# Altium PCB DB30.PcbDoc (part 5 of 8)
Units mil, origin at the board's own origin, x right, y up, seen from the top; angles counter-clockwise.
Board outline 3236.22 x 4456.69 mil, 8 copper layers (Top Layer, MidLayer1, MidLayer2, GND-Layer5, MidLayer3, VCC, MidLayer4, Bottom Layer), stack 61.8 mil thick; 219 components, 472 nets, 1811 pads, 1561 vias.
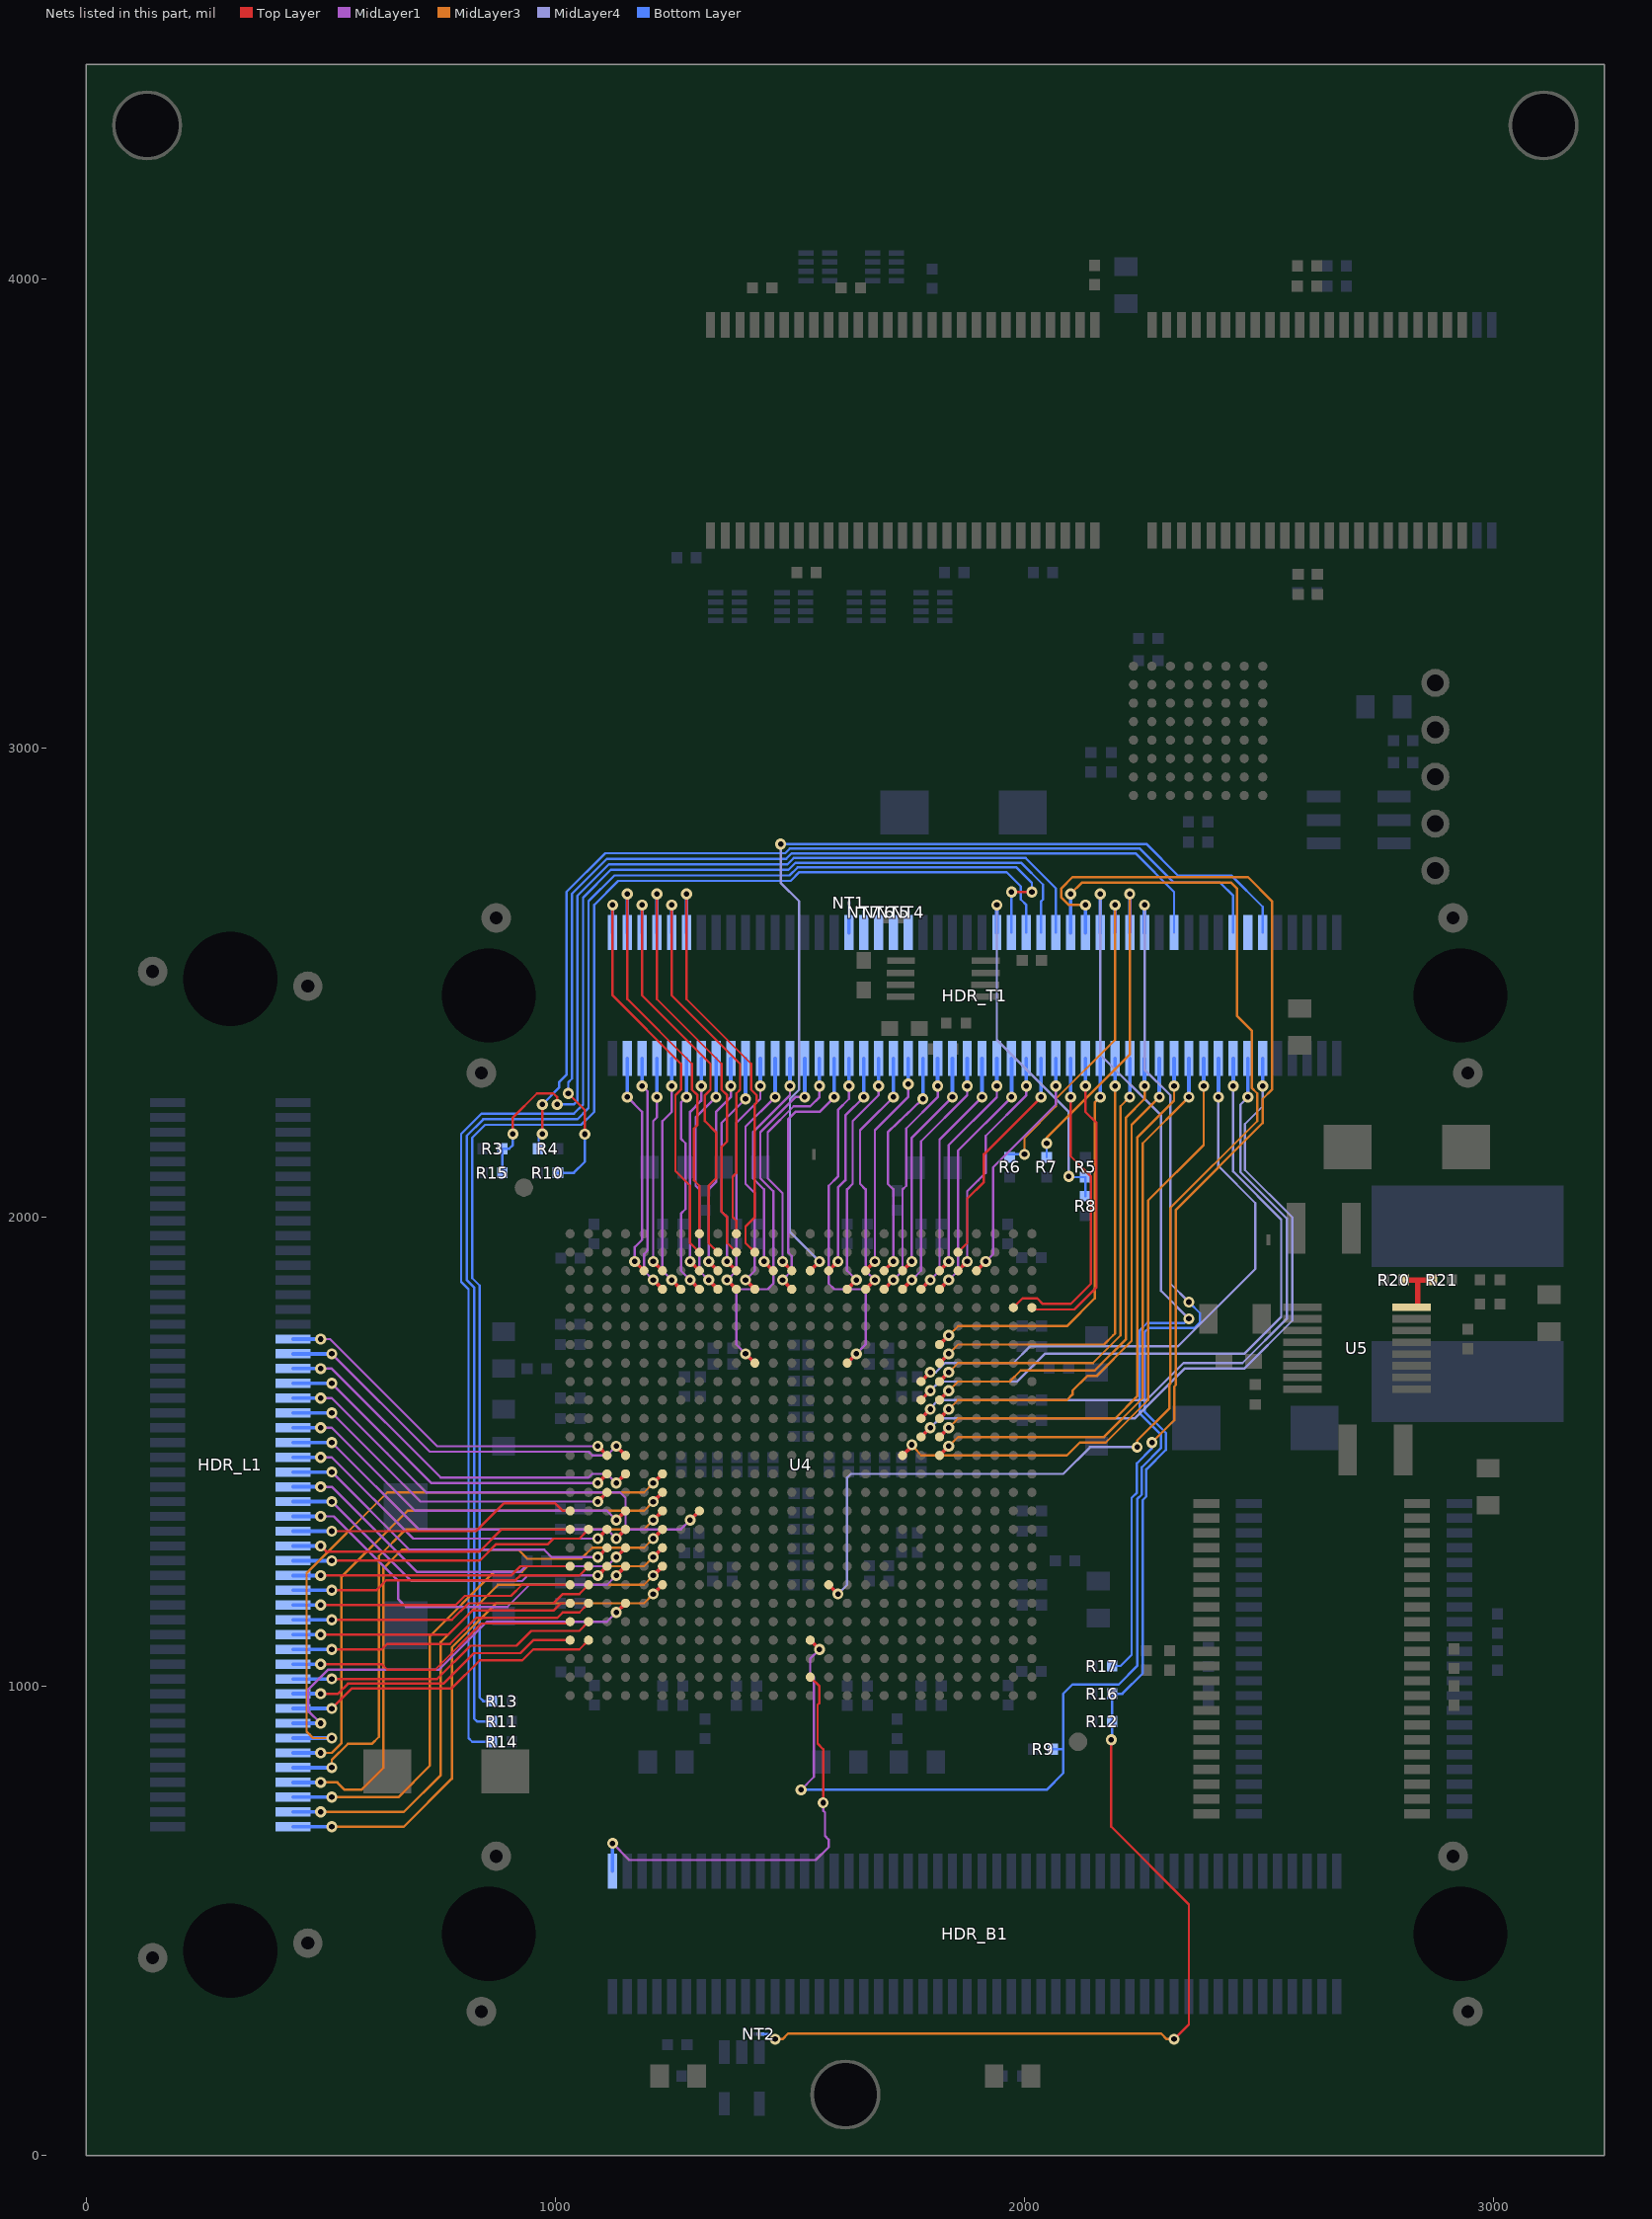
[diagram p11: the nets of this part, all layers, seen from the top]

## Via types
v1: diameter 23.62, hole 11.81, Top Layer to Bottom Layer, 944 vias
v2: diameter 23.62, hole 11.81, Top Layer to Bottom Layer, tented both sides, 477 vias
v3: diameter 27.56, hole 15.75, Top Layer to Bottom Layer, 139 vias
v4: diameter 23.62, hole 11.81, Top Layer to Bottom Layer, tented top, 1 vias

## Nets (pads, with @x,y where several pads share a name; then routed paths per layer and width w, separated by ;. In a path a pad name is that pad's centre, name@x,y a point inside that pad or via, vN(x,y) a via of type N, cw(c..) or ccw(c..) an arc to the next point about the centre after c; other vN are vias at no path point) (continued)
EXTEND_B16: HDR_L1.34 U4.N3 | length 772
  Top Layer w7.87: v1(1090.55,1511.81) U4.N3@1110.24,1492.13
  MidLayer1 w5: v2(500,1740.16) 519.68,1740.16 748.03,1511.81 956.69,1511.81 968.5,1511.81 v1(1090.55,1511.81)
  Bottom Layer w7.87: HDR_L1.34@440.94,1740.15 v2(500,1740.16)
EXTEND_B17: HDR_L1.36 U4.N4 | length 814.7
  Top Layer w7.87: v1(1129.92,1511.81) U4.N4@1149.61,1492.13
  MidLayer1 w5: v2(523.62,1708.66) 732.29,1500 956.69,1500 968.5,1500 1070.87,1500 1078.74,1492.13 1110.23,1492.13 v1(1129.92,1511.81)
  Bottom Layer w7.87: HDR_L1.36@440.94,1708.66 v2(523.62,1708.66)
EXTEND_B18: HDR_L1.38 U4.P4 | length 824.4
  Top Layer w7.87: v1(1129.92,1433.07) U4.P4@1149.61,1452.76
  MidLayer1 w5: v2(500,1677.17) 523.62,1677.17 755.91,1444.88 956.69,1444.88 968.5,1444.88 1070.87,1444.88 1078.74,1452.76 1110.23,1452.76 v1(1129.92,1433.07)
  Bottom Layer w7.87: HDR_L1.38@440.94,1677.16 v2(500,1677.17)
EXTEND_B19: HDR_L1.40 U4.P3 | length 765.5
  Top Layer w7.87: v1(1090.55,1433.07) U4.P3@1110.24,1452.76
  MidLayer1 w5: v2(523.62,1645.67) 736.22,1433.07 956.69,1433.07 968.5,1433.07 v1(1090.55,1433.07)
  Bottom Layer w7.87: HDR_L1.40@440.94,1645.67 v2(523.62,1645.67)
EXTEND_B20: HDR_L1.42 U4.T8 | length 1032.8
  Top Layer w7.87: v1(1287.4,1354.33) U4.T8@1307.09,1374.02
  MidLayer1 w5: v2(500,1614.17) 523.62,1614.17 641.73,1496.06 724.41,1413.39 956.69,1413.39 968.5,1413.39 1003.94,1413.39 1137.8,1413.39 1149.61,1401.57 1149.61,1342.52 1157.48,1334.65 1267.72,1334.65 v1(1287.4,1354.33)
  Bottom Layer w7.87: HDR_L1.42@440.94,1614.17 v2(500,1614.17)
EXTEND_B21: HDR_L1.44 U4.R3 | length 755.7
  Top Layer w7.87: v1(1090.55,1393.7) U4.R3@1110.24,1413.39
  MidLayer1 w5: v2(523.62,1582.68) 712.6,1393.7 956.69,1393.7 968.5,1393.7 v1(1090.55,1393.7)
  Bottom Layer w7.87: HDR_L1.44@440.94,1582.67 v2(523.62,1582.68)
EXTEND_B22: HDR_L1.46 U4.T4 | length 798.4
  Top Layer w7.87: v1(1129.92,1354.33) U4.T4@1149.61,1374.02
  MidLayer1 w5: v2(500,1551.18) 523.62,1551.18 700.79,1374.02 956.69,1374.02 968.5,1374.01 1110.24,1374.01 v1(1129.92,1354.33)
  Bottom Layer w7.87: HDR_L1.46@440.94,1551.18 v2(500,1551.18)
EXTEND_B23: HDR_L1.48 U4.U4 | length 801.6
  Top Layer w7.87: v1(1129.92,1314.96) U4.U4@1149.61,1334.65
  MidLayer1 w5: v2(523.62,1519.68) 708.66,1334.65 956.69,1334.65 968.5,1334.65 996.06,1334.65 1110.24,1334.64 v1(1129.92,1314.96)
  Bottom Layer w7.87: HDR_L1.48@440.94,1519.68 v2(523.62,1519.68)
EXTEND_B24: HDR_L1.50 U4.U3 | length 749.2
  Top Layer w7.87: v1(1090.55,1314.96) U4.U3@1110.24,1334.65
  MidLayer1 w5: v2(500,1488.19) 523.62,1488.19 696.85,1314.96 956.69,1314.96 968.5,1314.96 996.06,1314.96 v1(1090.55,1314.96)
  Bottom Layer w7.87: HDR_L1.50@440.94,1488.19 v2(500,1488.19)
EXTEND_B25: HDR_L1.52 U4.V3 | length 752.5
  Top Layer w7.87: v1(1090.55,1275.59) U4.V3@1110.24,1295.28
  MidLayer1 w5: v2(523.62,1456.69) 688.98,1291.34 956.69,1291.34 968.5,1291.34 976.38,1291.34 992.13,1275.59 v1(1090.55,1275.59)
  Bottom Layer w7.87: HDR_L1.52@440.94,1456.69 v2(523.62,1456.69)
EXTEND_B26: HDR_L1.54 U4.V4 | length 804.9
  Top Layer w7.87: v1(1129.92,1275.59) U4.V4@1149.61,1295.28
  MidLayer1 w5: v2(500,1425.2) 523.62,1425.2 704.72,1244.09 925.2,1244.09 937.01,1255.91 956.69,1255.91 968.5,1255.91 1110.24,1255.91 v1(1129.92,1275.59)
  Bottom Layer w7.87: HDR_L1.54@440.94,1425.19 v2(500,1425.2)
EXTEND_B27: HDR_L1.56 U4.W3 | length 752.5
  Top Layer w7.87: v1(1090.55,1236.22) U4.W3@1110.24,1255.91
  MidLayer1 w5: v2(523.62,1393.7) 692.91,1224.41 929.13,1224.41 940.94,1236.22 956.69,1236.22 968.5,1236.22 v1(1090.55,1236.22)
  Bottom Layer w7.87: HDR_L1.56@440.94,1393.7 v2(523.62,1393.7)
EXTEND_B28: HDR_L1.58 U4.W4 | length 961.4
  Top Layer w7.87: v1(1129.92,1236.22) U4.W4@1149.61,1255.91
  MidLayer1 w5: v2(500,1362.21) 527.56,1362.21 665.3,1224.46 665.3,1185.7 681.8,1169.2 897.55,1169.2 944.88,1216.54 956.69,1216.54 968.5,1216.54 1110.24,1216.54 ; 996.06,1216.54 1110.24,1216.54 ; v1(1129.92,1236.22) 1110.24,1216.54
  Bottom Layer w7.87: HDR_L1.58@440.94,1362.2 v2(500,1362.21)
EXTEND_B29: HDR_L1.60 U4.T1 | length 621.5
  Top Layer w5: v2(523.62,1330.71) 830.71,1330.71 889.76,1389.76 956.69,1389.76 968.5,1389.76 1000,1389.76 1015.75,1374.02 U4.T1@1031.5,1374.02
  Bottom Layer w7.87: HDR_L1.60@440.94,1330.71 v2(523.62,1330.71)
EXTEND_B30: HDR_L1.62 U4.U1 | length 615
  Top Layer w5: v2(500,1299.21) 511.81,1287.4 838.58,1287.4 885.83,1334.65 956.69,1334.65 968.5,1334.65 U4.U1@1031.5,1334.65
  Bottom Layer w7.87: HDR_L1.62@440.94,1299.21 v2(500,1299.21)
EXTEND_B31: HDR_L1.64 U4.U2 | length 657.6
  Top Layer w5: v2(523.62,1267.72) 838.58,1267.72 874.02,1303.15 956.69,1303.15 968.5,1303.15 984.25,1303.15 996.06,1314.96 1051.18,1314.96 U4.U2@1070.87,1334.65
  Bottom Layer w7.87: HDR_L1.64@440.94,1267.71 v2(523.62,1267.72)
EXTEND_B32: HDR_L1.66 U4.W1 | length 598.7
  Top Layer w5: v2(500,1236.22) 905.51,1236.22 925.2,1255.91 952.76,1255.91 968.5,1255.91 U4.W1@1031.5,1255.91
  Bottom Layer w7.87: HDR_L1.66@440.94,1236.22 v2(500,1236.22)
EXTEND_B33: HDR_L1.68 U4.W2 | length 651.1
  Top Layer w5: v2(523.62,1204.72) 618.4,1204.72 639.9,1226.22 915.2,1226.22 925.2,1236.22 952.76,1236.22 968.5,1236.22 1051.18,1236.22 U4.W2@1070.87,1255.91
  Bottom Layer w7.87: HDR_L1.68@440.94,1204.72 v2(523.62,1204.72)
EXTEND_B34: HDR_L1.70 U4.Y1 | length 608.5
  Top Layer w5: v2(500,1173.23) 787.4,1173.23 807.09,1192.91 905.51,1192.91 929.13,1216.54 952.76,1216.54 968.5,1216.54 U4.Y1@1031.5,1216.54
  Bottom Layer w7.87: HDR_L1.70@440.94,1173.23 v2(500,1173.23)
EXTEND_B35: HDR_L1.72 U4.Y2 | length 660.9
  Top Layer w5: v2(523.62,1141.73) 779.53,1141.73 814.96,1177.17 952.76,1177.17 968.5,1177.17 996.06,1177.17 1015.75,1196.85 1051.18,1196.85 U4.Y2@1070.87,1216.54
  Bottom Layer w7.87: HDR_L1.72@440.94,1141.73 v2(523.62,1141.73)
EXTEND_B36: HDR_L1.74 U4.AA1 | length 618.3
  Top Layer w5: v2(500,1110.24) 771.65,1110.24 822.83,1161.42 952.76,1161.42 968.5,1161.42 996.06,1161.42 1011.81,1177.17 U4.AA1@1031.5,1177.17
  Bottom Layer w7.87: HDR_L1.74@440.94,1110.23 v2(500,1110.24)
EXTEND_B37: HDR_L1.76 U4.AA2 | length 670.7
  Top Layer w5: v2(523.62,1078.74) 629.92,1078.74 641.73,1090.55 775.59,1090.55 830.71,1145.67 952.76,1145.67 968.5,1145.67 1003.94,1145.67 1015.75,1157.48 1051.18,1157.48 U4.AA2@1070.87,1177.17
  Bottom Layer w7.87: HDR_L1.76@440.94,1078.74 v2(523.62,1078.74)
EXTEND_B38: HDR_L1.78 U4.AB1 | length 637.8
  Top Layer w5: v2(500,1047.25) 629.92,1047.25 641.73,1035.43 744.09,1035.43 842.52,1133.86 952.76,1133.86 968.5,1133.86 1027.56,1133.86 U4.AB1@1031.5,1137.8
  Bottom Layer w7.87: HDR_L1.78@440.94,1047.24 v2(500,1047.25)
EXTEND_B39: HDR_L1.80 U4.AB2 | length 680.5
  Top Layer w5: v2(523.62,1015.75) 748.03,1015.75 818.9,1086.61 917.32,1086.61 948.82,1118.11 952.76,1118.11 968.5,1118.11 1011.81,1118.11 1051.18,1118.11 U4.AB2@1070.87,1137.8
  Bottom Layer w7.87: HDR_L1.80@440.94,1015.74 v2(523.62,1015.75)
EXTEND_B40: HDR_L1.82 U4.AC1 | length 637.8
  Top Layer w5: v2(500,984.25) 536.6,984.25 558.1,1005.75 761.65,1005.75 826.77,1070.87 925.2,1070.87 952.76,1098.43 968.5,1098.42 1011.81,1098.42 U4.AC1@1031.5,1098.43
  Bottom Layer w7.87: HDR_L1.82@440.94,984.25 v2(500,984.25)
EXTEND_B41: HDR_L1.84 U4.AC2 | length 690.3
  Top Layer w5: v2(523.62,952.75) 566.62,995.75 779.21,995.75 838.58,1055.12 929.13,1055.12 952.76,1078.74 968.5,1078.74 1051.18,1078.74 U4.AC2@1070.87,1098.43
  Bottom Layer w7.87: HDR_L1.84@440.94,952.75 v2(523.62,952.75)
EXTEND_B42: HDR_L1.86 U4.AA4 | length 894.4
  Top Layer w7.87: v1(1129.92,1157.48) U4.AA4@1149.61,1177.17
  MidLayer1 w5: v2(500,921.26) 473.3,947.96 473.3,992.9 516.16,1035.76 639.36,1035.76 752.29,1035.76 854.33,1137.8 952.76,1137.8 968.5,1137.8 1110.24,1137.8 v1(1129.92,1157.48)
  Bottom Layer w7.87: HDR_L1.86@440.94,921.26 v2(500,921.26)
EXTEND_B43: HDR_L1.88 U4.P6 | length 1326.2
  Top Layer w7.87: v1(1208.66,1433.07) U4.P6@1228.35,1452.76
  MidLayer3 w5: v2(523.62,889.76) 483.44,889.76 469.9,903.3 469.9,1241.5 641.79,1413.39 956.69,1413.39 968.5,1413.39 1188.98,1413.39 v1(1208.66,1433.07)
  Bottom Layer w7.87: HDR_L1.88@440.94,889.76 v2(523.62,889.76)
EXTEND_B44: HDR_L1.90 U4.R6 | length 1224.9
  Top Layer w7.87: v1(1208.66,1393.7) U4.R6@1228.35,1413.39
  MidLayer3 w5: v2(500,858.27) 523.62,858.27 543.8,878.45 543.8,1232.78 685.04,1374.02 956.69,1374.02 968.5,1374.02 1039.37,1374.02 1188.98,1374.02 v1(1208.66,1393.7)
  Bottom Layer w7.87: HDR_L1.90@440.94,858.26 v2(500,858.27)
EXTEND_B45: HDR_L1.92 U4.T6 | length 1249.2
  Top Layer w7.87: v1(1208.66,1354.33) U4.T6@1228.35,1374.02
  MidLayer3 w5: v2(523.62,826.77) 523.62,843.22 557.8,877.4 608.76,877.4 623.86,892.5 623.86,1277.4 681.1,1334.65 956.69,1334.65 968.5,1334.65 1188.98,1334.65 v1(1208.66,1354.33)
  Bottom Layer w7.87: HDR_L1.92@440.94,826.77 v2(523.62,826.77)
EXTEND_B46: HDR_L1.94 U4.U6 | length 1289.2
  Top Layer w7.87: v1(1208.66,1314.96) U4.U6@1228.35,1334.65
  MidLayer3 w5: v2(500,795.28) 535.43,795.28 551.18,779.53 586.61,779.53 633.86,826.77 633.86,1251.97 673.23,1291.34 921.26,1291.34 940.94,1271.65 956.69,1271.65 968.5,1271.65 1055.12,1271.65 1078.74,1295.28 1188.98,1295.28 v1(1208.66,1314.96)
  Bottom Layer w7.87: HDR_L1.94@440.94,795.27 v2(500,795.28)
EXTEND_B47: HDR_L1.96 U4.V6 | length 1169
  Top Layer w7.87: v1(1208.66,1275.59) U4.V6@1228.35,1295.28
  MidLayer3 w5: v2(523.62,763.78) 665.35,763.78 732.28,830.71 732.28,1106.3 870.08,1244.09 929.13,1244.09 940.94,1255.91 956.69,1255.91 968.5,1255.91 1188.97,1255.9 v1(1208.66,1275.59)
  Bottom Layer w7.87: HDR_L1.96@440.95,763.78 v2(523.62,763.78)
EXTEND_B48: HDR_L1.98 U4.W6 | length 1170.3
  Top Layer w7.87: v1(1208.66,1236.22) U4.W6@1228.35,1255.91
  MidLayer3 w5: v2(500,732.28) 677.16,732.28 755.91,811.02 755.91,1094.49 877.95,1216.54 956.69,1216.54 968.5,1216.54 1188.97,1216.53 v1(1208.66,1236.22)
  Bottom Layer w7.87: HDR_L1.98@440.94,732.28 v2(500,732.28)
EXTEND_B49: HDR_L1.100 U4.Y6 | length 1164.8
  Top Layer w7.87: v1(1208.66,1196.85) U4.Y6@1228.35,1216.54
  MidLayer3 w5: v2(523.62,700.79) 677.16,700.79 779.53,803.15 779.53,1082.68 874.02,1177.17 956.69,1177.17 968.5,1177.17 1188.97,1177.16 v1(1208.66,1196.85)
  Bottom Layer w7.87: HDR_L1.100@440.94,700.78 v2(523.62,700.79)
EXTEND_C0: HDR_T1.89 U4.M20 | length 1569.7
  Top Layer w7.87: U4.M20@1779.53,1531.5 v1(1799.21,1551.18)
  MidLayer4 w5: v1(1799.21,1551.18) 1818.9,1570.87 1988.19,1570.87 2078.74,1570.87 2094.49,1570.87 2234.77,1570.87 2341.07,1677.17 2468.5,1677.17 2570.87,1779.53 2570.87,1999.66 2470,2100.53 2470,2198.35 2507.87,2236.22 v2(2507.87,2279.53)
  Bottom Layer w7.87: v2(2507.87,2279.53) HDR_T1.89@2507.88,2338.58 v2(2507.87,2279.53)
EXTEND_C1: HDR_T1.87 U4.L20 | length 1471.8
  Top Layer w7.87: U4.L20@1779.53,1570.87 v1(1799.21,1590.55)
  MidLayer4 w5: v1(1799.21,1590.55) 1814.96,1610.24 1968.5,1610.24 2078.74,1610.24 2094.49,1610.24 2260,1610.24 2338.74,1688.98 2464.57,1688.98 2559.06,1783.46 2559.06,1997.33 2460,2096.39 2460,2239.53 v2(2476.38,2255.9)
  Bottom Layer w7.87: v2(2476.38,2255.9) HDR_T1.87@2476.38,2338.58
EXTEND_C2: HDR_T1.85 U4.K20 | length 1434.7
  Top Layer w7.87: U4.K20@1779.53,1610.24 v1(1799.21,1629.92)
  MidLayer4 w5: v1(1799.21,1629.92) 1818.9,1649.61 1984.25,1649.61 2043.31,1708.66 2074.8,1708.66 2090.55,1708.66 2468.5,1708.66 2547.24,1787.4 2547.24,1995 2444.88,2097.37 v2(2444.88,2279.53)
  Bottom Layer w7.87: v2(2444.88,2279.53) HDR_T1.85@2444.88,2338.58
EXTEND_C3: HDR_T1.83 U4.J20 | length 1293.5
  Top Layer w7.87: U4.J20@1779.53,1649.61 v1(1799.21,1669.29)
  MidLayer4 w5: v1(1799.21,1669.29) 1811.21,1669.29 1830.9,1688.98 1976.38,1688.98 2011.81,1724.41 2074.8,1724.41 2090.55,1724.41 2326.77,1724.41 2492.13,1889.76 2492.13,2030 2413.38,2108.74 v2(2413.38,2255.9)
  Bottom Layer w7.87: v2(2413.38,2255.9) HDR_T1.83@2413.39,2338.58
EXTEND_C4: HDR_T1.81 U4.N19 | length 1368.3
  Top Layer w7.87: U4.N19@1740.16,1492.13 v1@1759.84,1511.81
  MidLayer3 w5: v1(1759.84,1514.76) 1779.53,1492.13 2078.74,1492.13 2090.55,1492.13 2118.11,1519.69 2173.23,1519.69 2263.78,1610.24 2263.78,2035.43 2381.89,2153.54 v2(2381.89,2279.53)
  Bottom Layer w7.87: v2(2381.89,2279.53) HDR_T1.81@2381.89,2338.58
EXTEND_C5: HDR_T1.79 U4.N21 | length 1248.8
  Top Layer w7.87: U4.N21@1818.9,1492.13 v1(1838.58,1511.81)
  MidLayer3 w5: v1(1838.58,1511.81) 1858.27,1531.5 2078.74,1531.5 2090.55,1531.5 2169.29,1531.5 2251.97,1614.17 2251.97,2157.48 v2(2350.39,2255.9)
  Bottom Layer w7.87: v2(2350.39,2255.9) HDR_T1.79@2350.4,2338.58
EXTEND_C6: HDR_T1.77 U4.M21 | length 1210.2
  Top Layer w7.87: U4.M21@1818.9,1531.5 v1(1838.58,1551.18)
  MidLayer3 w5: v1(1838.58,1551.18) 1858.27,1570.87 2007.87,1570.87 2078.74,1570.87 2090.55,1570.87 2192.91,1570.87 2240.16,1618.11 2240.16,2169.29 2318.89,2248.03 v2(2318.89,2279.53)
  Bottom Layer w7.87: v2(2318.89,2279.53) HDR_T1.77@2318.9,2338.58
EXTEND_C7: HDR_T1.75 U4.L21 | length 1109.4
  Top Layer w7.87: U4.L21@1818.9,1570.87 v1(1838.58,1590.55)
  MidLayer3 w5: v1(1838.58,1590.55) 1858.27,1610.24 2078.74,1610.24 2090.55,1610.24 2102.36,1622.05 2102.36,1629.92 2133.86,1661.42 2153.54,1661.42 2228.35,1736.22 2228.35,2196.85 v2(2287.4,2255.9)
  Bottom Layer w7.87: v2(2287.4,2255.9) HDR_T1.75@2287.4,2338.58
EXTEND_C8: HDR_T1.73 U4.K21 | length 1066.2
  Top Layer w7.87: U4.K21@1818.9,1610.24 v1(1838.58,1629.92)
  MidLayer3 w5: v1(1838.58,1629.92) 1858.27,1649.61 1968.5,1649.61 1992.13,1673.23 2078.74,1673.23 2090.55,1673.23 2149.61,1673.23 2216.54,1740.16 2216.54,2212.6 2255.9,2251.97 v2(2255.9,2279.53)
  Bottom Layer w7.87: v2(2255.9,2279.53) HDR_T1.73@2255.91,2338.58
EXTEND_C9: HDR_T1.71 U4.J21 | length 1025.3
  Top Layer w7.87: U4.J21@1818.9,1649.61 v1(1838.58,1669.29)
  MidLayer3 w5: v1(1838.58,1669.29) 1858.27,1688.98 2078.74,1688.98 2090.55,1688.98 2145.67,1688.98 2204.72,1748.03 2204.72,2236.22 v2(2224.41,2255.9)
  Bottom Layer w7.87: v2(2224.41,2255.9) HDR_T1.71@2224.41,2338.58
EXTEND_C10: HDR_T1.69 U4.H21 | length 986.7
  Top Layer w7.87: U4.H21@1818.9,1688.98 v1(1838.58,1708.66)
  MidLayer3 w5: v1(1838.58,1708.66) 1858.27,1728.35 2078.74,1728.35 2090.55,1728.35 2169.29,1728.35 2188.98,1748.03 2192.91,1751.97 v2(2192.91,2279.53)
  Bottom Layer w7.87: v2(2192.91,2279.53) HDR_T1.69@2192.91,2338.58
EXTEND_C11: HDR_T1.67 U4.G21 | length 888.2
  Top Layer w7.87: U4.G21@1818.9,1728.35 v1(1838.58,1748.03)
  MidLayer3 w5: v1(1838.58,1748.03) 1858.27,1767.72 2078.74,1767.72 2090.55,1767.72 2149.61,1826.77 2149.61,2244.1 v2(2161.42,2255.9)
  Bottom Layer w7.87: v2(2161.42,2255.9) HDR_T1.67@2161.42,2338.58
EXTEND_C12: HDR_T1.65 U4.E26 | length 657
  Top Layer w5: U4.E26@2015.75,1807.09 2019.69,1803.15 2078.74,1803.15 2090.55,1803.15 2106.3,1803.15 2153.54,1850.39 2153.54,2200.79 2129.92,2224.41 v2(2129.92,2279.53)
  Bottom Layer w7.87: v2(2129.92,2279.53) HDR_T1.65@2129.92,2338.58
EXTEND_C13: HDR_T1.63 U4.E25 | length 694.6
  Top Layer w5: U4.E25@1976.38,1807.09 1996.06,1826.77 2016.73,1826.77 2027.07,1826.77 2038.88,1814.96 2078.74,1814.96 2090.55,1814.96 2098.43,1814.96 2141.73,1858.27 2141.73,2086.61 2098.42,2129.92 v2(2098.42,2255.9)
  Bottom Layer w7.87: v2(2098.42,2255.9) HDR_T1.63@2098.43,2338.58
EXTEND_C14: HDR_T1.61 U4.C23 | length 522.9
  Top Layer w7.87: U4.C23@1897.64,1885.83 v1(1917.32,1905.51)
  MidLayer1 w5: v1(1917.32,1905.51) 1933.07,1921.26 1933.07,2027.56 1933.07,2039.37 1933.07,2106.3 2066.93,2240.16 v2(2066.93,2279.53)
  Bottom Layer w7.87: v2(2066.93,2279.53) HDR_T1.61@2066.93,2338.58
EXTEND_C15: HDR_T1.59 U4.B22 | length 486.8
  Top Layer w5: U4.B22@1858.27,1925.2 1877.95,1944.88 1877.95,2027.56 1877.95,2039.37 1913.39,2074.8 1913.39,2133.86 v2(2035.43,2255.9)
  Bottom Layer w7.87: v2(2035.43,2255.9) HDR_T1.59@2035.43,2338.58
EXTEND_C16: HDR_T1.57 U4.C22 | length 513.1
  Top Layer w7.87: U4.C22@1858.27,1885.83 v1(1877.95,1905.51)
  MidLayer1 w5: v1(1877.95,1905.51) 1877.95,2027.56 1877.95,2039.37 1877.95,2055.12 1901.57,2078.74 1917.32,2094.49 1917.32,2173.23 2003.94,2259.84 v2(2003.93,2279.53)
  Bottom Layer w7.87: v2(2003.93,2279.53) HDR_T1.57@2003.94,2338.58
EXTEND_C17: HDR_T1.55 U4.D21 | length 555.7
  Top Layer w7.87: U4.D21@1818.9,1846.46 v1(1838.58,1866.14)
  MidLayer1 w5: v1(1838.58,1866.14) 1858.27,1885.83 1858.27,2027.56 1858.27,2039.37 1858.27,2141.73 v2(1972.44,2255.9)
  Bottom Layer w7.87: v2(1972.44,2255.9) HDR_T1.55@1972.44,2338.58
EXTEND_C18: HDR_T1.53 U4.C21 | length 503.3
  Top Layer w7.87: U4.C21@1818.9,1885.83 v1(1838.58,1905.51)
  MidLayer1 w5: v1(1838.58,1905.51) 1838.58,2027.56 1838.58,2039.37 1838.58,2153.54 1940.94,2255.9 v2(1940.94,2279.53)
  Bottom Layer w7.87: v2(1940.94,2279.53) HDR_T1.53@1940.95,2338.58
EXTEND_C19: HDR_T1.51 U4.D20 | length 545.9
  Top Layer w7.87: U4.D20@1779.53,1846.46 v1(1799.21,1866.14)
  MidLayer1 w5: v1(1799.21,1866.14) 1818.9,1885.83 1818.9,2027.56 1818.9,2039.37 1818.9,2165.36 v2(1909.45,2255.9)
  Bottom Layer w7.87: v2(1909.45,2255.9) HDR_T1.51@1909.45,2338.58
EXTEND_C20: HDR_T1.49 U4.D19 | length 663.4
  Top Layer w7.87: U4.D19@1740.16,1846.46 v1(1759.84,1866.14)
  MidLayer1 w5: v1(1759.84,1866.14) 1779.53,1885.83 ; 1779.53,2000 1779.53,1885.83 ; v2(1877.95,2279.53) 1877.95,2259.84 1779.53,2161.42 1779.53,2039.37 1779.53,2027.56 1779.53,1885.83
  Bottom Layer w7.87: v2(1877.95,2279.53) HDR_T1.49@1877.95,2338.58
EXTEND_C21: HDR_T1.47 U4.C19 | length 496.8
  Top Layer w7.87: U4.C19@1740.16,1885.83 v1(1759.84,1905.51)
  MidLayer1 w5: v1(1759.84,1905.51) 1759.84,2027.56 1759.84,2039.37 1759.84,2169.29 v2(1846.46,2255.9)
  Bottom Layer w7.87: v2(1846.46,2255.9) HDR_T1.47@1846.46,2338.58
EXTEND_C22: HDR_T1.45 U4.D18 | length 539.4
  Top Layer w7.87: U4.D18@1700.79,1846.46 v1(1720.47,1866.14)
  MidLayer1 w5: v1(1720.47,1866.14) 1740.16,1885.83 1740.16,2027.56 1740.16,2039.37 1740.16,2059.05 1748.03,2066.93 1748.03,2188.97 1814.96,2255.9 v2(1814.96,2279.53)
  Bottom Layer w7.87: v2(1814.96,2279.53) HDR_T1.45@1814.96,2338.58
EXTEND_C23: HDR_T1.43 U4.C18 | length 498
  Top Layer w7.87: U4.C18@1700.79,1885.83 v1(1720.47,1905.51)
  MidLayer1 w5: v1(1720.47,1905.51) 1720.47,2027.56 1720.47,2039.37 1720.47,2059.06 1708.66,2070.87 1708.66,2181.1 v2(1783.46,2251.96)
  Bottom Layer w7.87: v2(1783.46,2251.96) HDR_T1.43@1783.47,2338.58
EXTEND_C24: HDR_T1.41 U4.C17 | length 490.3
  Top Layer w7.87: U4.C17@1661.42,1885.83 v1(1681.1,1905.51)
  MidLayer1 w5: v1(1681.1,1905.51) 1681.1,2000 1681.1,2027.56 1681.1,2039.37 1681.1,2185.04 1751.97,2255.9 v2@1751.97,2279.53
  Bottom Layer w7.87: v2@1751.97,2279.53 HDR_T1.41@1751.97,2338.58
  other v2: 1751.97,2283.46
EXTEND_C25: HDR_T1.39 U4.D17 | length 620.6
  Top Layer w7.87: U4.D17@1661.42,1846.46 v1(1681.1,1866.14)
  MidLayer1 w5: 1665.35,2200.79 v2(1720.47,2255.9) 1649.61,2185.04 1649.61,2070.87 1661.42,2059.06 1661.42,2039.37 1661.42,2027.56 1661.42,1885.83 v1(1681.1,1866.14)
  Bottom Layer w7.87: v2(1720.47,2255.9) HDR_T1.39@1720.47,2338.58
EXTEND_C26: HDR_T1.37 U4.D16 | length 536.2
  Top Layer w7.87: U4.D16@1622.05,1846.46 v1(1641.73,1866.14)
  MidLayer1 w5: v1(1641.73,1866.14) 1622.05,1885.83 1622.05,2027.56 1622.05,2039.37 1622.05,2059.06 1633.86,2070.87 1633.86,2204.72 1688.98,2259.84 v2(1688.97,2279.53)
  Bottom Layer w7.87: v2(1688.97,2279.53) HDR_T1.37@1688.98,2338.58
EXTEND_C27: HDR_T1.35 U4.C15 | length 483.7
  Top Layer w7.87: U4.C15@1582.68,1885.83 v1(1602.36,1905.51)
  MidLayer1 w5: v1(1602.36,1905.51) 1602.36,2027.56 1602.36,2039.37 1602.36,2062.99 1618.11,2078.74 1618.11,2216.53 v2(1657.48,2255.9)
  Bottom Layer w7.87: v2(1657.48,2255.9) HDR_T1.35@1657.48,2338.58
EXTEND_C28: HDR_T1.33 U4.H16 | length 751.1
  Top Layer w7.87: U4.H16@1622.05,1688.98 v1(1641.73,1708.66)
  MidLayer1 w5: v2(1625.98,2279.53) 1625.98,2251.97 1602.36,2228.35 1602.36,2086.61 1582.68,2066.93 1582.68,2039.37 1582.68,2027.56 1582.68,1992.13 1582.68,1858.27 1594.49,1846.46 1653.54,1846.46 1661.42,1838.58 1661.42,1728.35 v1(1641.73,1708.66)
  Bottom Layer w7.87: v2(1625.98,2279.53) HDR_T1.33@1625.99,2338.58
EXTEND_C29: HDR_T1.31 U4.D13 | length 582.4
  Top Layer w7.87: v1(1484.25,1866.14) U4.D13@1503.94,1846.46
  MidLayer1 w5: v1(1484.25,1866.14) 1503.94,1885.83 1503.94,1917.32 1496.06,1925.2 1496.06,2027.56 1496.06,2039.37 1496.06,2208.66 1511.81,2224.41 1562.99,2224.41 v2(1594.49,2255.9)
  Bottom Layer w7.87: v2(1594.49,2255.9) HDR_T1.31@1594.49,2338.58
EXTEND_C30: HDR_T1.29 U4.C13 | length 540.4
  Top Layer w7.87: v1(1484.25,1905.51) U4.C13@1503.94,1885.83
  MidLayer1 w5: v1(1484.25,1905.51) 1484.25,2027.56 1484.25,2039.37 1484.25,2051.18 1452.76,2082.68 1452.76,2181.1 1507.87,2236.22 1543.31,2236.22 1562.99,2255.9 v2(1562.99,2279.53)
  Bottom Layer w7.87: v2(1562.99,2279.53) HDR_T1.29@1562.99,2338.58
EXTEND_C31: HDR_T1.27 U4.H11 | length 795.2
  Top Layer w7.87: v1(1405.51,1708.66) U4.H11@1425.2,1688.98
  MidLayer1 w5: v1(1405.51,1708.66) 1385.83,1728.35 1385.83,1838.58 1393.7,1846.46 1452.76,1846.46 1464.57,1858.27 1464.57,1992.13 1464.57,2027.56 1464.57,2039.37 1464.57,2055.12 1437.01,2082.68 1437.01,2181.1 1511.81,2255.9 v2(1531.5,2255.9)
  Bottom Layer w7.87: v2(1531.5,2255.9) HDR_T1.27@1531.5,2338.58
EXTEND_C32: HDR_T1.25 U4.C12 | length 503.3
  Top Layer w7.87: v1(1444.88,1905.51) U4.C12@1464.57,1885.83
  MidLayer1 w5: v1(1444.88,1905.51) 1444.88,2027.56 1444.88,2039.37 1444.88,2059.06 1421.26,2082.68 1421.26,2181.1 1500,2259.84 v2(1500,2279.53)
  Bottom Layer w7.87: v2(1500,2279.53) HDR_T1.25@1500,2338.58
EXTEND_C33: HDR_T1.23 U4.D11 | length 542.7
  Top Layer w7.87: v1(1405.51,1866.14) U4.D11@1425.2,1846.46
  MidLayer1 w5: v1(1405.51,1866.14) 1425.19,1885.83 1425.19,2027.56 1425.2,2039.37 1425.2,2051.18 1405.51,2070.87 1405.51,2192.91 v2(1468.5,2255.9)
  Bottom Layer w7.87: v2(1468.5,2255.9) HDR_T1.23@1468.5,2338.58
EXTEND_C34: HDR_T1.21 U4.D10 | length 529.6
  Top Layer w7.87: v1(1366.14,1866.14) U4.D10@1385.83,1846.46
  MidLayer1 w5: v1(1366.14,1866.14) 1385.82,1885.83 1385.82,2027.56 1385.83,2039.37 1385.83,2200.79 1437.01,2251.97 v2(1437.01,2279.53)
  Bottom Layer w7.87: v2(1437.01,2279.53) HDR_T1.21@1437.01,2338.58
EXTEND_C35: HDR_T1.19 U4.C10 | length 483.1
  Top Layer w7.87: v1(1366.14,1905.51) U4.C10@1385.83,1885.83
  MidLayer1 w5: v1(1366.14,1905.51) 1366.14,2000 1354.33,2011.81 1354.33,2027.56 1354.33,2039.37 1354.33,2200.79 v2(1405.51,2251.97)
  Bottom Layer w7.87: v2@1405.51,2255.9 HDR_T1.19@1405.51,2338.58
EXTEND_C36: HDR_T1.17 U4.C9 | length 480.5
  Top Layer w7.87: v1(1326.77,1905.51) U4.C9@1346.46,1885.83
  MidLayer1 w5: v1(1326.77,1905.51) 1326.77,2027.56 1326.77,2039.37 1326.77,2059.05 1342.52,2074.8 1342.52,2224.41 1374.02,2255.91 v2(1374.02,2279.53)
  Bottom Layer w7.87: v2(1374.02,2279.53) HDR_T1.17@1374.02,2338.58
EXTEND_C37: HDR_T1.15 U4.D9 | length 529.6
  Top Layer w7.87: v1(1326.77,1866.14) U4.D9@1346.46,1846.46
  MidLayer1 w5: v1(1326.77,1866.14) 1307.09,1885.83 1307.09,2027.56 1307.09,2039.37 1307.09,2059.06 1299.21,2066.93 1299.21,2212.6 v2(1342.52,2255.9)
  Bottom Layer w7.87: v2(1342.52,2255.9) HDR_T1.15@1342.52,2338.58
EXTEND_C38: HDR_T1.13 U4.C8 | length 470.7
  Top Layer w7.87: v1(1287.4,1905.51) U4.C8@1307.09,1885.83
  MidLayer1 w5: v1(1287.4,1905.51) 1287.4,2027.56 1287.4,2039.37 1287.4,2224.41 1311.02,2248.03 v2(1311.02,2279.53)
  Bottom Layer w7.87: v2(1311.02,2279.53) HDR_T1.13@1311.02,2338.58
EXTEND_C39: HDR_T1.11 U4.D8 | length 635.5
  Top Layer w7.87: v1(1287.4,1866.14) U4.D8@1307.09,1846.46
  MidLayer1 w5: 1267.72,2000 1267.72,1885.83 ; v2(1279.53,2255.9) 1267.72,2244.09 1267.72,2167 1277.4,2157.32 1277.4,2017.28 1267.72,2007.6 1267.72,1885.83 ; v1(1287.4,1866.14) 1267.72,1885.83
  Bottom Layer w7.87: v2(1279.53,2255.9) HDR_T1.11@1279.53,2338.58
EXTEND_C40: HDR_T1.12 U4.B11 | length 926.4
  Top Layer w5: v2(1279.53,2688.98) 1279.53,2464.57 1417.32,2326.77 1417.32,2271.65 1429.13,2259.84 1429.13,2244.09 1425.2,2240.16 1425.2,2039.37 1425.2,2027.56 1425.2,2000 1405.51,1980.32 1405.51,1944.88 U4.B11@1425.2,1925.2
  Bottom Layer w7.87: HDR_T1.12@1279.53,2606.3 v2(1279.53,2688.98)
EXTEND_C41: HDR_T1.9 U4.D7 | length 516.6
  Top Layer w7.87: v1(1248.03,1866.14) U4.D7@1267.72,1846.46
  MidLayer1 w5: v1(1248.03,1866.14) 1228.35,1885.83 1228.35,2027.56 1228.35,2039.37 1228.35,2204.72 1248.03,2224.41 v2(1248.03,2279.53)
  Bottom Layer w7.87: v2(1248.03,2279.53) HDR_T1.9@1248.03,2338.58
EXTEND_C42: HDR_T1.10 U4.A10 | length 830
  Top Layer w5: v2(1248.03,2665.35) 1248.03,2472.44 1393.7,2326.78 1393.7,2271.65 1385.83,2263.78 1385.83,2094.49 1377.95,2086.61 1377.95,2043.31 1377.95,2027.56 1377.95,2000 1385.83,1992.13 U4.A10@1385.83,1964.57
  Bottom Layer w7.87: HDR_T1.10@1248.03,2606.3 v2(1248.03,2665.35)
EXTEND_C43: HDR_T1.7 U4.C6 | length 464.2
  Top Layer w7.87: v1(1208.66,1905.51) U4.C6@1228.35,1885.83
  MidLayer1 w5: v1(1208.66,1905.51) 1208.66,2027.56 1208.66,2039.37 1208.66,2204.72 1216.54,2212.6 v2(1216.54,2255.9)
  Bottom Layer w7.87: v2(1216.54,2255.9) HDR_T1.7@1216.54,2338.58
EXTEND_C44: HDR_T1.8 U4.B10 | length 926.4
  Top Layer w5: v2(1216.54,2688.98) 1216.54,2464.57 1354.33,2326.77 1354.33,2271.65 1366.14,2259.84 1366.14,2161.42 1354.33,2149.61 1354.33,2043.31 1354.33,2027.56 1354.33,2011.81 1366.14,2000 1366.14,1944.88 U4.B10@1385.83,1925.2
  Bottom Layer w7.87: HDR_T1.8@1216.54,2606.3 v2(1216.54,2688.98)
EXTEND_C45: HDR_T1.5 U4.D6 | length 516.6
  Top Layer w7.87: v1(1208.66,1866.14) U4.D6@1228.35,1846.46
  MidLayer1 w5: v2(1185.04,2279.53) 1196.85,2267.72 1196.85,2039.37 1196.85,2027.56 1196.85,1929.13 1188.98,1921.26 1188.98,1885.83 v1(1208.66,1866.14)
  Bottom Layer w7.87: v2(1185.04,2279.53) HDR_T1.5@1185.04,2338.58
EXTEND_C46: HDR_T1.6 U4.B9 | length 948
  Top Layer w5: v2(1185.04,2665.35) 1185.04,2472.44 1330.71,2326.77 1330.71,2271.65 1318.9,2259.84 1318.9,2204.72 1342.52,2181.1 1342.52,2082.68 1326.77,2066.93 1326.77,2043.31 1326.77,2027.56 1326.77,1944.88 U4.B9@1346.46,1925.2
  Bottom Layer w7.87: HDR_T1.6@1185.04,2606.3 v2(1185.04,2665.35) HDR_T1.6@1185.04,2606.3
EXTEND_C47: HDR_T1.3 U4.C5 | length 480.5
  Top Layer w7.87: v1(1169.29,1905.51) U4.C5@1188.98,1885.83
  MidLayer1 w5: v2(1153.54,2255.9) 1185.04,2224.41 1185.04,2039.37 1185.04,2027.56 1185.04,1951.77 1169.29,1936.02 v1(1169.29,1905.51)
  Bottom Layer w7.87: v2(1153.54,2255.9) HDR_T1.3@1153.54,2338.58
EXTEND_C48: HDR_T1.4 U4.A8 | length 936.3
  Top Layer w5: v2(1153.54,2688.98) 1153.54,2464.57 1291.34,2326.77 1291.34,2271.65 1303.15,2259.84 1303.15,2196.85 1295.28,2188.98 1295.28,2078.74 1307.09,2066.93 1307.09,2043.31 1307.09,2027.56 U4.A8@1307.09,1964.57
  Bottom Layer w7.87: 1153.54,2665.35 HDR_T1.4@1153.54,2606.3 v2(1153.54,2688.98)
EXTEND_C49: HDR_T1.2 U4.B8 | length 885.6
  Top Layer w5: v2(1122.05,2665.35) 1122.05,2472.44 1267.72,2326.77 1267.72,2271.65 1255.91,2259.84 1255.91,2098.43 1287.4,2066.93 1287.4,2043.31 1287.4,2027.56 1287.4,1944.88 U4.B8@1307.09,1925.2
  Bottom Layer w7.87: HDR_T1.2@1122.05,2606.3 v2(1122.05,2665.35)
FB: R20.2 R21.1 U5.8 | length 120.2
  Top Layer w7.87: U5.8@2842.51,1807.09 U5.8@2842.51,1808.25
  Top Layer w11.81: R20.2@2808.58,1866.14 2838.58,1866.14 ; U5.8@2838.58,1807.09 2838.58,1808.25 2838.58,1866.14 ; R21.1@2868.58,1866.14 2838.58,1866.14
FPGA_CCLK: HDR_T1.66 R17.1 | length 2397.7
  MidLayer3 w5: v2(2129.92,2665.35) 2094.49,2665.35 2078.74,2681.1 2078.74,2700.79 2102.36,2724.41 2476.38,2724.41 2527.56,2673.23 2527.56,2271.65 2507.87,2251.97 2507.87,2200.79 2322.83,2015.75 2322.83,1642.67 2319.21,1639.05 2319.21,1567.24 v1(2271.65,1519.68)
  Bottom Layer w5: R17.1@2186.54,1043.31 2204.72,1043.31 2228.34,1066.92 2228.34,1401.57 2239.78,1413.01 2239.78,1475.21 2270.67,1506.1 v1@2270.67,1519.68
  Bottom Layer w7.87: HDR_T1.66@2129.92,2606.3 v2(2129.92,2665.35)
FPGA_CLK: HDR_B1.2 U4.AE14 | length 927.6
  Top Layer w5: U4.AE14@1543.31,1019.68 1562.99,1000 1562.99,964.57 1559.06,960.63 1559.06,877.95 1570.87,866.14 v1(1570.87,751.97)
  MidLayer1 w5: v2(1122.05,665.35) 1157.48,629.92 1555.12,629.92 1582.68,657.48 1582.68,673.23 1574.8,681.1 1574.8,731.31 1570.87,735.25 v1(1570.87,751.97)
  Bottom Layer w7.87: HDR_B1.2@1122.05,606.3 v2(1122.05,665.35)
FPGA_CLK1: HDR_T1.90 U4.C14 | length 2106.3
  Top Layer w7.87: U4.C14@1543.31,1885.83 v1(1562.99,1905.51)
  MidLayer4 w5: v1(1480.31,2795.28) 1480.31,2712.6 1519.68,2673.23 1519.68,2271.65 1500,2251.97 1500,1968.51 v1(1562.99,1905.51)
  Bottom Layer w5: v1(1480.31,2795.28) 2259.84,2795.28 2326.77,2728.35 2440.94,2728.35 2507.87,2661.42 HDR_T1.90@2507.88,2606.3
FPGA_DIN: HDR_T1.64 U4.Y15 | length 2695.6
  Top Layer w7.87: U4.Y15@1582.68,1216.54 v1(1602.36,1196.85)
  MidLayer3 w5: v2(2098.42,2688.98) 2122.05,2712.6 2440.94,2712.6 2452.76,2700.79 2452.76,2429.13 2484.25,2397.64 2484.25,2275.59 2496.06,2263.78 2496.06,2204.72 2311.02,2019.68 2311.02,1645 2309.21,1643.19 2309.21,1592.68 2240.16,1523.62 v1(2240.16,1509.84)
  MidLayer4 w5: v1(1602.36,1196.85) 1622.05,1216.54 1622.05,1444.88 1629.92,1452.76 2082.68,1452.76 2139.76,1509.84 v1(2240.16,1509.84)
  Bottom Layer w7.87: v2(2098.42,2688.98) HDR_T1.64@2098.43,2606.3
FPGA_DONE: HDR_T1.74 NT2.2 R12.1 R16.1 | length 3685.6
  Top Layer w5: v1(2185.04,885.83) 2185.04,700.79 2350.39,535.43 2350.39,279.53 v1(2318.9,248.03)
  MidLayer3 w5: v1(1468.5,248.03) 1484.25,248.03 1496.06,259.84 2291.34,259.84 2303.15,248.03 v1(2318.9,248.03)
  MidLayer4 w5: v2(2255.9,2665.35) 2255.9,2314.96 2311.02,2259.84 2311.02,1858.27 v1(2350.39,1818.9)
  Bottom Layer w5: NT2.2@1440.94,258.86 1457.68,258.86 v1(1468.5,248.03) ; R12.1@2185.04,925.2 R12.1@2186.54,925.2 ; v1@2186.54,885.83 R16.1@2186.54,984.25 2208.66,984.25 2251.96,1027.55 2251.96,1396.91 2259.78,1404.73 2259.78,1462.5 2301.34,1504.06 2301.34,1539.94 2256,1585.28 2256,1754.56 2265.54,1764.1 2362.62,1764.1 2374.02,1775.5 2374.02,1795.28 v1(2350.39,1818.9)
  Bottom Layer w7.87: HDR_T1.74@2255.91,2606.3 v2(2255.9,2665.35)
FPGA_ID0: HDR_T1.42 NT4.1
FPGA_ID1: HDR_T1.40 NT5.1
FPGA_ID2: HDR_T1.38 NT6.1
FPGA_ID3: HDR_T1.36 NT7.1
FPGA_INIT: HDR_T1.68 R9.1 U4.AC14 | length 3233.5
  Top Layer w7.87: U4.AC14@1543.31,1098.43 v1(1562.99,1078.74)
  MidLayer1 w5: v1(1523.62,779.53) 1551.18,807.09 1551.18,1019.69 1543.31,1027.56 1543.31,1059.05 v1(1562.99,1078.74)
  MidLayer4 w5: v2(2161.42,2688.98) 2161.42,2346.46 2291.34,2216.54 2291.34,1842.52 v1(2350.39,1783.46)
  Bottom Layer w5: v1(1523.62,779.53) 2047.24,779.53 2082.68,814.96 2082.68,984.25 2102.36,1003.94 2200.79,1003.94 2240.15,1043.3 2240.15,1399.24 2249.78,1408.87 2249.78,1466.64 2291.34,1508.2 2291.34,1535.8 2246,1581.14 2246,1758.7 2261.4,1774.1 2341.03,1774.1 v1(2350.39,1783.46) ; R9.1@2060.55,866.14 2082.68,866.14
  Bottom Layer w7.87: HDR_T1.68@2161.42,2606.3 v2(2161.42,2688.98)
FPGA_INSTALLED: HDR_T1.34 NT1.1 | length 55.2
  Bottom Layer w7.87: HDR_T1.34@1625.99,2606.3 NT1.1@1625.98,2661.42
FPGA_M0: HDR_T1.60 R14.1 | length 3208.1
  Bottom Layer w5: R14.1@864.64,881.89 822.84,881.89 814.96,889.76 814.96,1846.46 799.21,1862.2 799.21,2177.17 842.52,2220.47 1039.37,2220.47 1059.06,2240.16 1059.06,2681.1 1118.11,2740.16 1496.99,2740.16 1512.11,2755.28 1992.76,2755.28 2039.37,2708.66 2039.37,2677.17 2035.43,2673.23 HDR_T1.60@2035.43,2606.3
FPGA_M1: HDR_T1.58 R13.1 | length 3006.8
  Bottom Layer w5: R13.1@864.64,968.5 846.46,968.5 838.58,976.38 838.58,1854.33 822.83,1870.08 822.83,2169.29 850.39,2196.85 1055.12,2196.85 1082.68,2224.41 1082.68,2665.35 1133.86,2716.54 1501.66,2716.54 1520.4,2735.28 1961.57,2735.28 1992.13,2704.72 1992.13,2677.17 2003.94,2665.35 HDR_T1.58@2003.94,2606.3
FPGA_M2: HDR_T1.56 R11.1 | length 3148
  Top Layer w5: v2(1972.44,2692.91) v2(2015.75,2692.91)
  Bottom Layer w5: R11.1@864.64,925.2 832.88,925.2 826.77,931.3 826.77,1850.39 811.02,1866.14 811.02,2173.23 846.46,2208.66 1047.24,2208.66 1070.87,2232.28 1070.87,2673.23 1125.98,2728.35 1499.32,2728.35 1516.25,2745.28 1983.07,2745.28 2015.75,2712.6 v2(2015.75,2692.91) ; HDR_T1.56@1972.44,2606.3 v2@1972.44,2688.98
FPGA_PROG_CLK: HDR_T1.88
FPGA_PROG_PWR_ON: HDR_T1.86 R4.1 | length 2152.1
  Top Layer w5: v1(972.44,2177.17) 972.44,2200.79 v1(972.44,2240.16)
  Bottom Layer w5: R4.1@963.07,2145.66 964.57,2147.16 964.57,2169.29 v1(972.44,2177.17) ; v1(972.44,2240.16) 1007.87,2275.59 1007.87,2287.4 1023.62,2303.15 1023.62,2692.91 1106.3,2775.59 1490,2775.59 1499.68,2785.28 2246.22,2785.28 2318.9,2712.6 2417.32,2712.6 2444.88,2685.04 HDR_T1.86@2444.88,2606.3
FPGA_PROGRAM: HDR_T1.62 R3.1 R15.1 | length 1928
  Top Layer w5: v1(909.45,2177.17) 909.45,2212.6 960.63,2263.78 996.06,2263.78 1003.94,2255.91 v1(1003.94,2240.16)
  Bottom Layer w5: R15.1@887.32,2094.48 R3.1@887.32,2145.66 901.57,2145.66 909.45,2153.54 v1(909.45,2177.17) ; v1(1003.94,2240.16) 1039.37,2240.16 1047.24,2248.03 1047.24,2685.04 1114.17,2751.97 1494.66,2751.97 1507.97,2765.28 2002.44,2765.28 2066.93,2700.79 HDR_T1.62@2066.93,2606.3
FPGA_TCK: HDR_T1.72 R7.1 | length 717.6
  MidLayer3 w5: v1(2047.24,2157.48) 2047.24,2169.29 2059.06,2181.1 ; 2059.06,2181.1 2224.41,2346.45 v2(2224.41,2688.98)
  Bottom Layer w5: R7.1@2047.24,2127.48 v1(2047.24,2157.48)
  Bottom Layer w7.87: HDR_T1.72@2224.41,2606.3 v2(2224.41,2688.98)
FPGA_TDI: HDR_T1.78 R10.1 | length 2096.1
  Top Layer w5: v1(1027.56,2263.78) 1062.99,2228.35 v1(1062.99,2176.89)
  Bottom Layer w5: R10.1@1005.43,2094.48 1039.37,2094.48 1062.99,2118.11 v1(1062.99,2176.89) ; v1(1027.56,2263.78) 1027.56,2287.4 1035.43,2295.28 1035.43,2688.98 1110.24,2763.78 1492.33,2763.78 1503.83,2775.28 2236.54,2775.28 2318.9,2692.91 HDR_T1.78@2318.9,2606.3
FPGA_TDO: HDR_T1.54 R5.1 R8.1 | length 777.8
  MidLayer4 w5: v2(1940.94,2665.35) 1940.94,2377.95 2094.49,2224.41 v1(2094.49,2086.61)
  Bottom Layer w5: v1(2094.49,2086.61) 2095.99,2085.11 R5.1@2129.92,2085.11 R8.1@2129.92,2044.8
  Bottom Layer w7.87: HDR_T1.54@1940.95,2606.3 v2(1940.94,2665.35)
FPGA_TMS: HDR_T1.70 R6.1 | length 706.5
  MidLayer3 w5: v1(2000,2133.86) 2000,2169.29 2066.93,2236.22 2066.93,2251.97 2192.91,2377.95 v2(2192.91,2665.35)
  Bottom Layer w5: R6.1@1964.56,2135.35 1966.05,2133.86 1968.5,2133.86 v1(2000,2133.86)
  Bottom Layer w7.87: HDR_T1.70@2192.91,2606.3 v2(2192.91,2665.35)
